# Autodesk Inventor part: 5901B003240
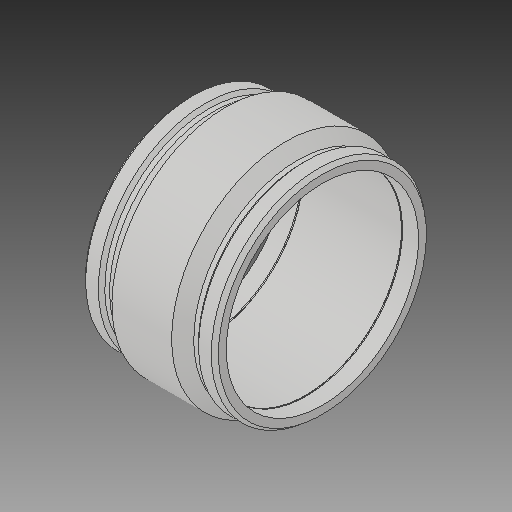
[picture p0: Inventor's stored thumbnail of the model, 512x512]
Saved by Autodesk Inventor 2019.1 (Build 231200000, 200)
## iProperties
Created: 2017-06
Part Number: 5901B003240
Material: Generic
Description: PLASSON IPS COUPLER 24''
Document SubType Name: Modeling
Designer: KIM
Mass: 8622.19 g
Surface Area: 6772.47 cm^2
Volume: 8622.19 cm^3
Density: 1 g/cm^3
Appearance: Default
Author: KIM
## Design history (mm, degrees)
derived "5901B.ipt"
feature "Solid1::5901B.ipt"
tag "TaggingFeature1"
body "Solid1"
other parameters: "d0" = 419.1, "d1" = 606.9, "d2" = 719.836, "d3" = 209.042, "d4" = 104.775, "d5" = 647.8524, "d6" = 485.52, "d7" = 606.9, "d8" = 168 deg, "d10" = 83.6168, "d11" = 27.87227, "d13" = 419.1, "d14" = 17.6296, "d18" = 606.9, "d19" = 3.52592, "d20" = 168 deg, "d22" = 676.64584, "d23" = 719.836, "d24" = 656.34646, "d25" = 135 deg, "d26" = 188.595, "d27" = 135 deg, "d29" = 355.6, "d30" = 15, "d31" = 146.685, "d34" = 5 deg, "d35" = 15, "d39" = 5 deg, "d41" = 4, "d42" = 14, "d43" = 0, "d45" = 4, "d46" = 14, "d47" = 0, "d48" = 3, "d49" = 0, "d50" = 3, "d51" = 0, "d52" = 60.62218, "d53" = 15.15555, "d55" = 209.042, "d_" = 606.9, "L_" = 419.1, "L_1" = 209.042, "D_" = 719.836, "A_" = 355.6, "d_2" = 12, "B_" = 355.6
